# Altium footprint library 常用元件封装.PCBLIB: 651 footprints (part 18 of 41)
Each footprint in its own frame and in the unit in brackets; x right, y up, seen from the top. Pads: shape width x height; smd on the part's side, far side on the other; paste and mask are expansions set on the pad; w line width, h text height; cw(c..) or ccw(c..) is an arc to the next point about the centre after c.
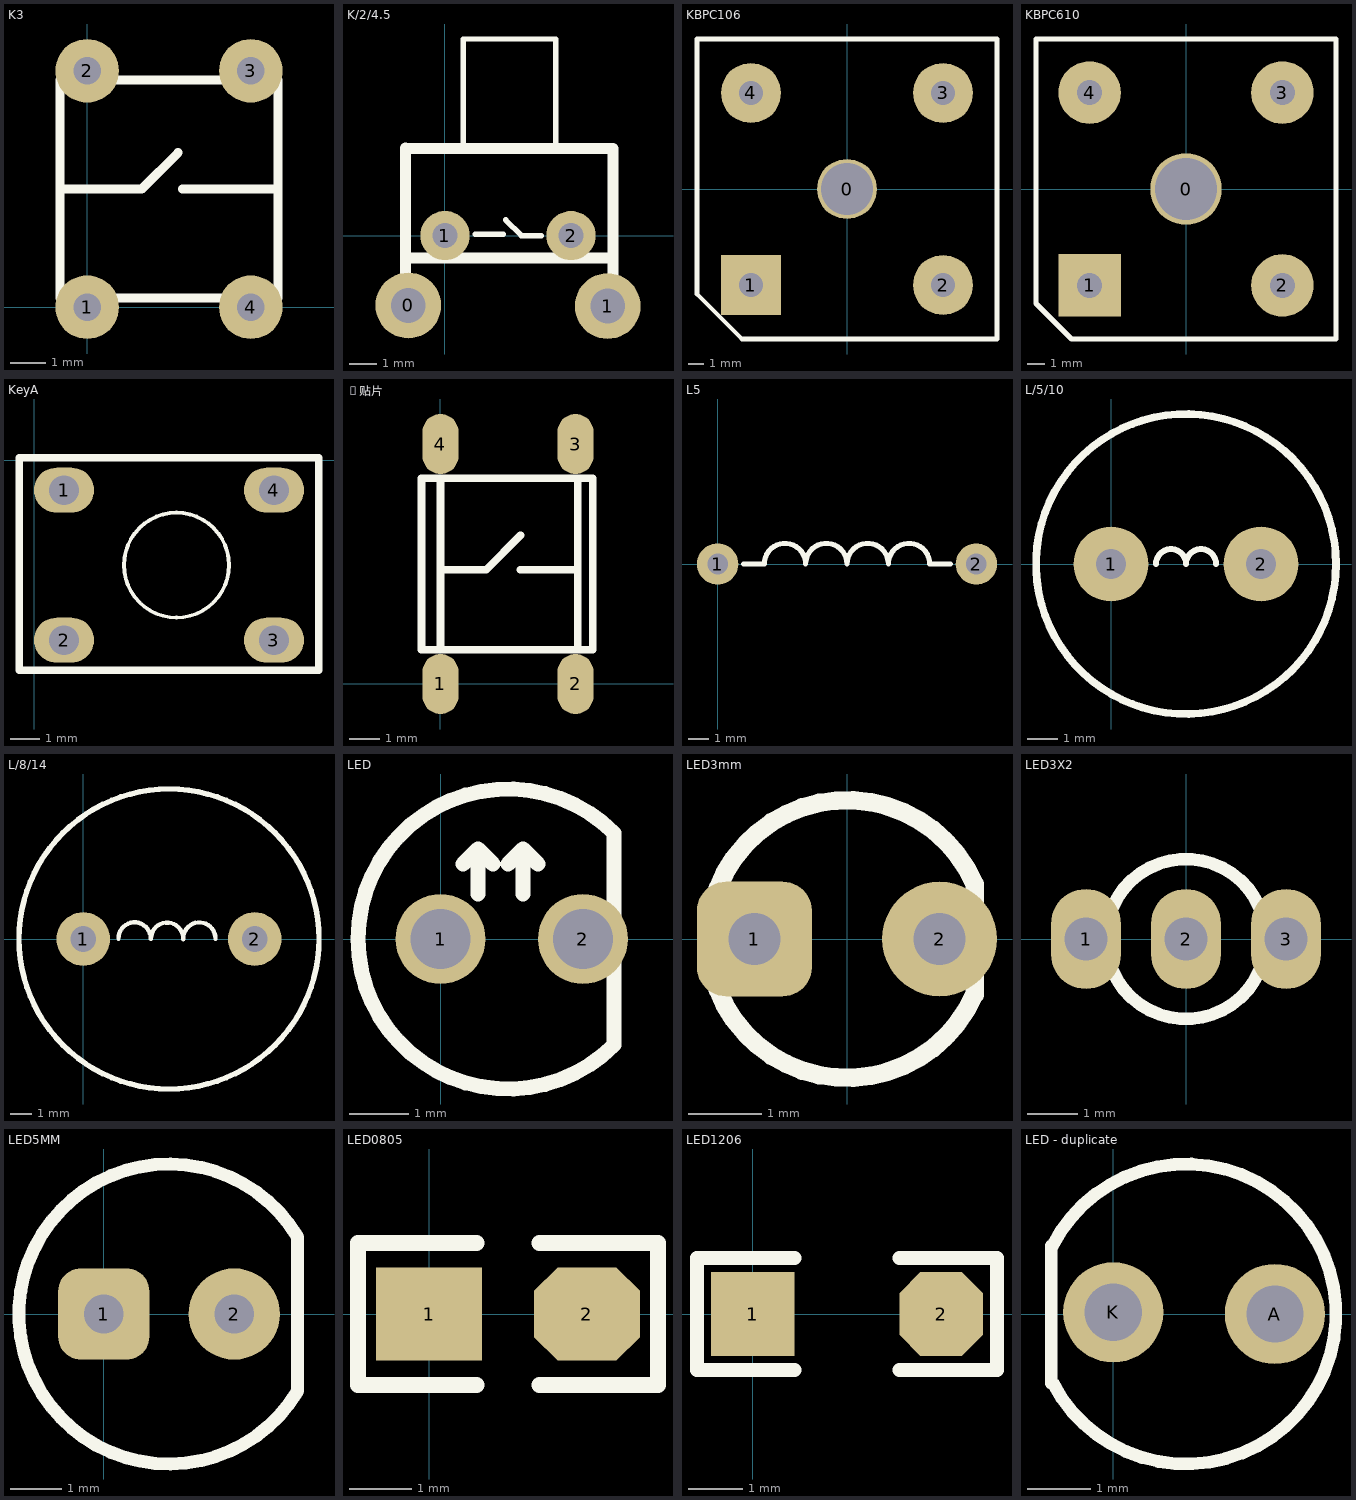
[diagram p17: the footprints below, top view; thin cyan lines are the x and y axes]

## K3 [mil] "6.604mmX4.572mm外宽6.35mmX6.35mm"
pads (4):
  round 70 hole 30: 1(0,0) 2(0,260) 3(180,260) 4(180,0)
TopOverlay:
  lines w10: -30,130 60,130 100,170 ; 105,130 210,130 ; -30,10 210,10 210,250 -30,250 -30,10

## K/2/4.5 [mm]
pads (4):
  round 2.4 hole 1.27: 0(-1.337,-2.55) 1(5.938,-2.575)
  round 1.8 hole 0.9: 1(0,0) 2(4.6,0)
TopOverlay:
  lines w0.2: 0.662,3.175 0.662,7.175 4.037,7.175 4.037,3.225 ; 1.103,0.04 2.119,0.04 ; 2.212,0.575 2.787,0 3.516,0
  lines w0.4: -1.437,-3.425 -1.437,-0.8 -1.437,3.2 ; -1.363,-0.825 6.137,-0.825 ; -1.363,3.175 6.137,3.175 6.137,-0.825 ; 6.137,-3.5 6.137,-0.825

## KBPC106 [mm]
pads (5):
  round 4 hole 3.5: 0(0,0)
  rect 4x4 hole 1.6: 1(-6.4,-6.4)
  round 4 hole 1.6: 2(6.4,-6.4) 3(6.4,6.4) 4(-6.4,6.4)
TopOverlay:
  lines w0.305: -10,-7 -7,-10 10,-10 10,10 -10,10 -10,-7

## KBPC610 [mm]
pads (5):
  round 4 hole 3.5: 0(0,0)
  rect 3.5x3.5 hole 1.4: 1(-5.4,-5.4)
  round 3.5 hole 1.4: 2(5.4,-5.4) 3(5.4,5.4) 4(-5.4,5.4)
TopOverlay:
  lines w0.305: -8.4,-6.4 -6.4,-8.4 8.4,-8.4 8.4,8.4 -8.4,8.4 -8.4,-6.4

## KeyA [mil]
pads (4):
  oval 80x60 hole 39.37: 1(40,-40) 2(40,-240) 3(320,-240) 4(320,-40)
TopOverlay:
  circle w5: c190,-140 r70
  lines w10: -20,-280 -20,-240 -20,0 -20,2.99 8.82,2.99 371.02,2.99 380,2.99 380,-240 380,-280 140,-280 -20,-280

## K贴片 [mm] "6mmX6mm"
pads (4):
  oval 1.2x2 smd: 1(0,0) 2(4.5,0) 3(4.5,8) 4(0,8)
TopOverlay:
  lines w0.254: 0,1.143 0,6.858 ; 0,3.81 1.524,3.81 2.667,4.953 ; 2.667,3.81 4.572,3.81 ; 4.572,1.143 4.572,6.858 ; -0.635,1.143 -0.635,6.858 5.08,6.858 5.08,1.143 -0.635,1.143

## L5 [mil] "12.7mm"
pads (2):
  round 80 hole 40: 1(0,0) 2(500,0)
TopOverlay:
  lines w10: 50,0 90,0 cw(c130,0) 170,0 cw(c210,0) 250,0 cw(c290,0) 330,0 cw(c370,0) 410,0 450,0

## L/5/10 [mm]
pads (2):
  round 2.5 hole 1.016: 1(0,0) 2(5,0)
TopOverlay:
  circle w0.254: c2.5,0 r5
  lines w0.2: 1.5,0 cw(c2,0) 2.5,0 cw(c3,0) 3.5,0

## L/8/14 [mm]
pads (2):
  round 2.5 hole 1.194: 1(0,0) 2(8,0)
TopOverlay:
  circle w0.254: c4,0 r7
  lines w0.2: 1.642,0.008 cw(c2.392,0.029) 3.142,0.004 ; 3.161,-0.004 cw(c3.911,0.017) 4.661,-0.008 ; 4.666,0.004 cw(c5.416,0.025) 6.166,0

## LED [mil]
pads (2):
  round 60 hole 40: 1(0,0) 2(95,0)
TopOverlay:
  lines w10: 15,50 25,60 ; 25,30 25,60 ; 35,50 25,60 ; 45,50 55,60 ; 55,30 55,60 ; 65,50 55,60 ; 115.71,-70.71 cw(c45,0) 115.71,70.71 115.71,-70.71

## LED3mm [mil]
height 39.37
pads (2):
  rrect50% 62x62 hole 28: 1(-50,0)
  round 62 hole 28: 2(50,0)
TopOverlay:
  lines w10: 68.94,-29.54 cw(c0,0) 68.94,29.54 ; 69,-30 69,29

## LED3X2 [mm] "直径3mm脚距2mm"
height 1
pads (3):
  oval 1.4x2 hole 0.864: 1(-2,0) 2(0,0) 3(2,0)
TopOverlay:
  circle w0.254: c0,0 r1.6

## LED5MM [mil]
height 39.37
pads (2):
  rrect50% 70x70 hole 30: 1(0,0)
  round 70 hole 30: 2(100,0)
TopOverlay:
  lines w10: 148.61,-59.17 cw(c50,0) 148.61,59.17 148.61,-59.17

## LED0805 [mm]
pads (2):
  rect 1.7x1.5 smd: 1(0,0)
  oct 1.7x1.5 smd: 2(2.54,0)
TopOverlay:
  lines w0.254: 0.762,-1.143 -1.143,-1.143 -1.143,1.143 0.762,1.143 ; 1.778,-1.143 3.683,-1.143 3.683,1.143 1.778,1.143

## LED1206 [mil]
pads (2):
  rect 60x60 smd: 1(0,0)
  oct 60x60 smd: 2(135,0)
TopOverlay:
  lines w10: 30,-40 -40,-40 -40,40 30,40 ; 105,-40 175,-40 175,40 105,40

## LED - duplicate [mil]
pads (2):
  round 62 hole 35.43: A(100,0) K(0,1)
TopOverlay:
  lines w7.87: -38.34,-42.75 -38.34,42.08 ; -37.62,42.22 cw(c45,0) -37.34,-42.75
